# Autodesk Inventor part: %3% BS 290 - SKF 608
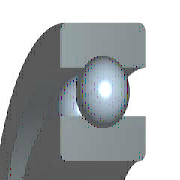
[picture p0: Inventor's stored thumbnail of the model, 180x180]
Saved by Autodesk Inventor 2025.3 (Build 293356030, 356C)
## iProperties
Created: 2024-01
Part Number: %3% BS 290 - SKF 608
Material: Acciaio, Dolce
Description: Cuscinetti a sfere a fila singola
Document SubType Name: Modeling
Standard: BS 290
Designer: R5800u
Standards Organization: BSI
Language: it-IT
Size Designation: SKF 608
Categories: <MemberInstance><Categories><Category DisplayName="Parti albero" InternalName="7f7aeb1f-a693-4053-b835-cee3144e0d98" Mnemonic="SHFT"><Category DisplayName="Cusc
Density: 7.85 g/cm^3
Appearance: Semilucidato
IsCustomPart: 0
Author: R5800u
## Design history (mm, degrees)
node "WorkPoint1"
node "WorkAxis1"
node "WorkPlane3"
node "WorkPlane4"
node "WorkPoint2"
pattern_circular "Seriepolare1" dims "d17" = 57.57143 (= msp_pocet), angle "d19" = 360 deg
body "Solid1"
node "Schizzo1"
revolve "Rivoluzione1" stored, may be unused: angle "d6" = 360 deg
revolve "Rivoluzione2" stored, may be unused: angle "d10" = 360 deg
node "Schizzo4"
revolve "Rivoluzione3" stored, may be unused: angle "d16" = 360 deg
fillet "Raccordo1" dims "d20" = 0.3 (= r)
sketch "Schizzo2"
  geometry: L1 (4, 7)-(11, 7); L2 (4, 0)-(4, 7); L3 (11, 0)-(4, 0); L4 (11, 7)-(11, 0); L5 (0, 0)-(0, 20); L6 (0, 0)-(0, 20); L7 (-7.2, 0)-(43.2, 0) reference
  constraints: 12 end point, 3 vertical, 2 horizontal, 1 collinear, 1 other
  dimensions: "d1" = 8 diameter of L1.start L5 (= Diam); "d3" = 22 diameter of L1.end L5 (= DD); "d5" = 7 distance of L2.start L1.start (= msp_mdtd2)
sketch "Schizzo3"
  geometry: L1 (8.76, 7)-(8.76, 5.18); L2 (6.24, 7)-(8.76, 7); L3 (6.24, 5.18)-(6.24, 7); L4 (6.24, 0)-(6.24, 1.82); L5 (8.76, 0)-(6.24, 0); L6 (8.76, 1.82)-(8.76, 0); L7 (11, 0)-(-11, 0) reference; L8 (11, 7)-(-11, 7) reference; L9 (0, -42.29)-(0, 61.29); L10 (0, 82.007)-(0, -63.007) reference; A1 r 2.1 centre (7.5, 3.5) between (8.76, 1.82) and (8.76, 5.18); A2 r 2.1 centre (7.5, 3.5) between (6.24, 5.18) and (6.24, 1.82)
  constraints: 14 end point, 4 collinear, 4 point on circle, 4 vertical, 2 centre point, 2 concentric, 2 horizontal, 2 point on line
  dimensions: "d9" = 4.2 diameter of A1 (= msp_mdtd6); "d21" = 6.24 distance between parallel lines of L9 L4 (= 0.5 x msp_d1); "d22" = 7.5 distance from line of L9 A1.centre (= 0.5 x msp_ds); "d23" = 8.76 distance between parallel lines of L9 L6 (= 0.5 x msp_dd1)
sketch "Schizzo5"
  geometry: L1 (7.5, 1.4)-(7.5, 5.6); L2 (8.76, 0)-(-8.76, 0) reference; L3 (7.5, 1.4)-(7.5, 5.6); A1 r 2.1 centre (7.5, 3.5) between (7.5, 1.4) and (7.5, 5.6); A2 r 2.1 centre (7.5, 3.5) between (8.76, 1.82) and (8.76, 5.18) reference
  constraints: 4 end point, 2 point on circle, 1 centre point, 1 concentric, 1 vertical
  dimensions: "d13" = 0 horizontal distance of A1.centre L1.start; "d15" = 4.2001 diameter of A1 (computed from msp_mdtd6)
other parameters: "Diam" = 8 [user parameter; used in 3 equation terms], "DD" = 22 [user parameter; used in 3 equation terms], "B" = 7 [user parameter; used in 1 equation term], "r" = 0.3 [user parameter; used in 1 equation term], "msp_ds" = 15 (= 0.5 x Diam + 0.5 x DD) [user parameter; used in 5 equation terms], "msp_d0" = 4.2 (= -0.3 x Diam + 0.3 x DD) [user parameter; used in 4 equation terms], "msp_d1" = 12.48 (= msp_ds - 0.6 x msp_d0) [user parameter; used in 1 equation term], "msp_dd1" = 17.52 (= msp_ds + 0.6 x msp_d0) [user parameter; used in 1 equation term], "msp_pom" = 22.5 (= 1.5 x msp_ds) [user parameter; used in 1 equation term], "msp_mdtd2" = 7 (= B) [user parameter; used in 3 equation terms], "msp_mdtd4" = 15 (= msp_ds) [user parameter], "msp_mdtd6" = 4.2 (= msp_d0) [user parameter; used in 2 equation terms], "msp_mdtd7" = 3.5 (= 0.5 x msp_mdtd2) [user parameter], "msp_pocet" = 57.57143 (computed from msp_d0, msp_pom) [user parameter; used in 1 equation term], "d2" = 72 (derived), "d4" = 19 (derived), "d7" = 0, "d8" = 15.6 (derived), "d11" = -7 (computed from msp_mdtd2), "d12" = 0 (derived), "d14" = 15.6001 (derived), "d26" = 0, "d27" = 0, "d28" = 0, "d29" = 0, "d30" = 0
